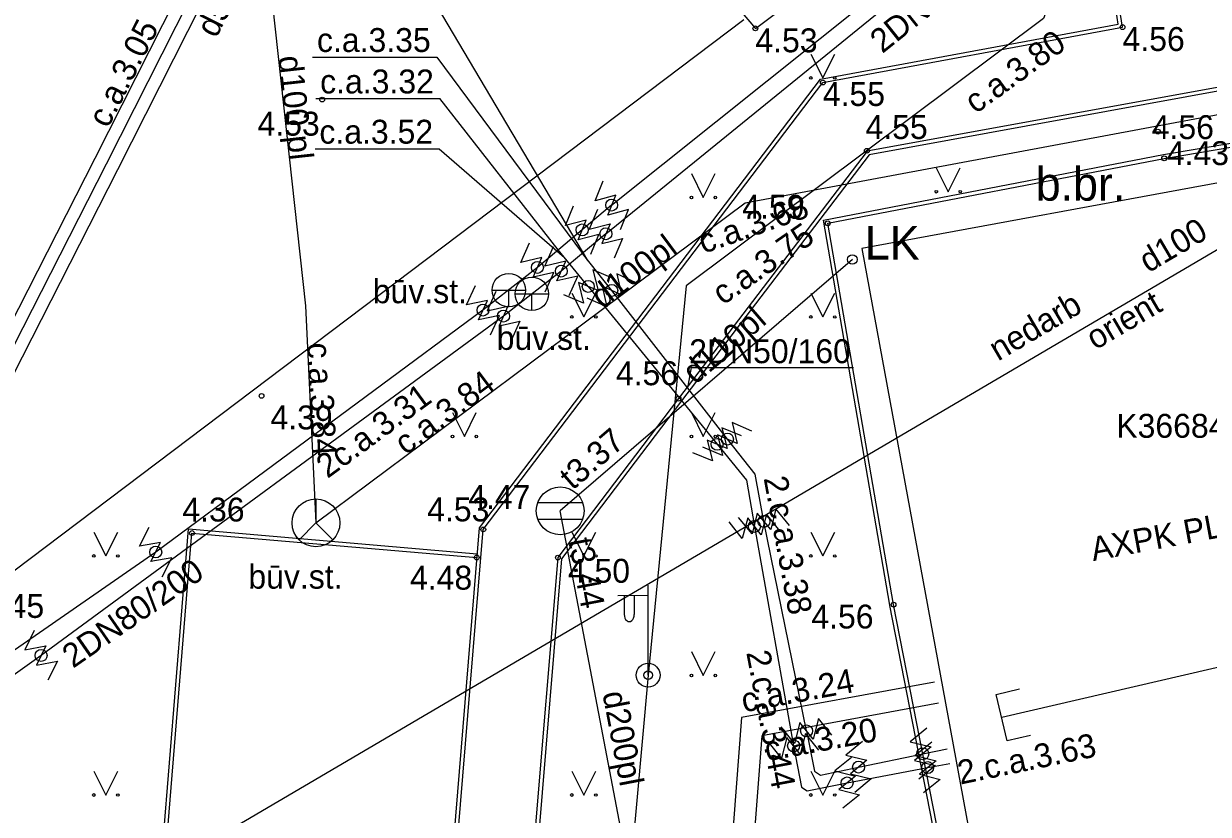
# Model space of a CAD drawing. Extents: x 484635 to 484808, y 278866 to 278977.
# Drawn here: x 484755.78 to 484780.57, y 278882.1 to 278898.63 of the extents above; entities that cross this region are included whole.
import ezdxf

# ---------------------------------------------------------------- set-up
doc = ezdxf.new("R2010")
doc.units = 0
for name, color, linetype in [('APGS_ACRL_####_####_#', 7, 'Continuous'), ('APGS_ELEM_####_####_#', 7, 'Continuous'), ('APGS_ELEM_####_TKST_#', 7, 'Continuous'), ('APGS_VADP_ZSPR_####_I', 7, 'Continuous'), ('BUVE_EKAS_####_####_#', 7, 'Continuous'), ('CELI_CAPM_####_####_#', 7, 'Continuous'), ('CELI_CSEG_####_TKST_#', 7, 'Continuous'), ('CKOM_ELEM_####_####_#', 7, 'Continuous'), ('ELEK_ELEM_####_TKST_#', 7, 'Continuous'), ('ELEK_VADP_ZSPR_TKST_I', 7, 'Continuous'), ('GAZE_VADP_KONT_####_#', 7, 'Continuous'), ('GAZE_VADP_VSP2_####_#', 7, 'Continuous'), ('GAZE_VADP_VSP2_TKST_#', 7, 'Continuous'), ('LKAN_ELEM_####_####_#', 7, 'Continuous'), ('LKAN_ELEM_PAST_TKST_#', 7, 'Continuous'), ('LKAN_VADP_PAST_####_#', 7, 'Continuous'), ('LKAN_VADP_PAST_####_I', 7, 'Continuous'), ('LKAN_VADP_PAST_TKST_I', 7, 'Continuous'), ('NORB_ZOGS_KONT_####_#', 7, 'Continuous'), ('NORB_ZOGS_ZSTP_####_#', 7, 'Continuous'), ('RELJ_AATZ_####_TKST_#', 7, 'Continuous'), ('RELJ_ELEM_####_####_#', 7, 'Continuous'), ('SAKK_ELEM_####_####_#', 7, 'Continuous'), ('SAKK_ELEM_####_TKST_#', 7, 'Continuous'), ('SAKK_KKAN_####_####_I', 7, 'Continuous'), ('SAKK_KKAN_####_TKST_I', 7, 'Continuous'), ('SILT_ELEM_####_####_#', 7, 'Continuous'), ('SILT_ELEM_####_TKST_#', 7, 'Continuous'), ('SILT_VADP_UDEN_####_I', 7, 'Continuous'), ('SILT_VADP_UDEN_TKST_I', 7, 'Continuous'), ('TERT_ELEM_####_####_#', 7, 'Continuous'), ('UDTK_ELEM_####_####_#', 7, 'Continuous'), ('UDTK_VADP_NEDR_####_#', 7, 'Continuous'), ('UDTK_VADP_NEDR_TKST_#', 7, 'Continuous'), ('UDTK_VADP_UDEN_####_I', 7, 'Continuous'), ('UDTK_VADP_UDEN_TKST_I', 7, 'Continuous')]:
    doc.layers.add(name, color=color, linetype=linetype)

msp = doc.modelspace()

# ---------------------------------------------------------------- linework, layer by layer
at = {"layer": 'APGS_ACRL_####_####_#'}
msp.add_lwpolyline([(484777.807, 278900.58), (484777.114, 278898.745), (484769.642, 278893.153), (484768.844, 278885.007), (484767.749, 278872.905), (484767.227, 278866.043)], dxfattribs=at)
at = {"layer": 'APGS_ELEM_####_####_#'}
for p, q in [((484768.844, 278885.007), (484768.844, 278886.89)), ((484768.844, 278886.674), (484768.209, 278886.669)), ((484768.344, 278886.67), (484768.344, 278886.278)), ((484768.554, 278886.672), (484768.554, 278886.278))]:
    msp.add_line(p, q, dxfattribs=at)
for radius in [0.25, 0.09]:
    msp.add_circle((484768.844, 278885.007), radius, dxfattribs=at)
msp.add_ellipse((484768.449, 278886.278), major_axis=(0, 0.151), ratio=0.695971, start_param=1.570796, end_param=4.712389, dxfattribs=at)
at = {"layer": 'APGS_VADP_ZSPR_####_I'}
msp.add_lwpolyline([(484777.807, 278900.58), (484777.114, 278898.745), (484769.642, 278893.153), (484768.844, 278885.007), (484767.749, 278872.905), (484767.227, 278866.043)], dxfattribs=at)
at = {"layer": 'BUVE_EKAS_####_####_#'}
for p, q in [((484784.53, 278895.998), (484773.318, 278893.935)), ((484773.318, 278893.935), (484775.96, 278879.576))]:
    msp.add_line(p, q, dxfattribs=at)
at = {"layer": 'CELI_CAPM_####_####_#'}
for p, q in [((484778.68, 278898.628), (484778.384, 278900.515)), ((484778.771, 278898.563), (484778.475, 278900.45)), ((484772.455, 278897.477), (484778.68, 278898.628)), ((484772.5, 278897.404), (484778.771, 278898.563)), ((484765.319, 278888.086), (484772.455, 278897.477)), ((484765.396, 278888.056), (484772.5, 278897.404)), ((484780.905, 278897.327), (484773.429, 278895.967)), ((484780.92, 278897.248), (484773.473, 278895.893)), ((484779.629, 278895.897), (484785.162, 278896.83)), ((484779.642, 278895.818), (484785.097, 278896.738)), ((484773.429, 278895.967), (484769.481, 278890.791)), ((484773.473, 278895.893), (484769.544, 278890.743)), ((484772.511, 278894.523), (484779.627, 278895.896)), ((484772.603, 278894.459), (484779.642, 278895.818)), ((484773.902, 278886.468), (484772.511, 278894.523)), ((484773.981, 278886.482), (484772.603, 278894.459)), ((484769.481, 278890.791), (484766.957, 278887.466)), ((484769.544, 278890.743), (484767.035, 278887.437)), ((484758.324, 278876.945), (484759.228, 278888.066)), ((484759.228, 278888.066), (484765.267, 278887.548)), ((484764.786, 278881.634), (484765.319, 278888.086)), ((484764.865, 278881.628), (484765.396, 278888.056)), ((484758.41, 278877.018), (484759.301, 278887.98)), ((484759.301, 278887.98), (484765.26, 278887.468)), ((484766.957, 278887.466), (484766.407, 278880.899)), ((484767.035, 278887.437), (484766.487, 278880.893)), ((484775.138, 278880.157), (484773.902, 278886.466)), ((484775.232, 278880.093), (484773.981, 278886.482))]:
    msp.add_line(p, q, dxfattribs=at)
at = {"layer": 'CKOM_ELEM_####_####_#'}
for points in [[(484768.264, 278894.333), (484768.431, 278894.748), (484767.999, 278894.633), (484768.166, 278895.048), (484767.734, 278894.932), (484767.901, 278895.347)], [(484767.646, 278893.814), (484767.813, 278894.228), (484767.381, 278894.114), (484767.548, 278894.528), (484767.116, 278894.414), (484767.284, 278894.828)], [(484767.788, 278894.751), (484767.614, 278894.339), (484768.048, 278894.447), (484767.874, 278894.035), (484768.308, 278894.143), (484768.135, 278893.731)], [(484766.693, 278893.024), (484766.874, 278893.433), (484766.438, 278893.332), (484766.619, 278893.741), (484766.183, 278893.64), (484766.364, 278894.049)], [(484767.191, 278892.946), (484767.373, 278893.355), (484766.937, 278893.256), (484767.12, 278893.664), (484766.684, 278893.565), (484766.866, 278893.973)], [(484768.103, 278893.312), (484767.69, 278893.485), (484767.799, 278893.051), (484767.387, 278893.224), (484767.496, 278892.791), (484767.084, 278892.963)], [(484768.597, 278893.216), (484768.189, 278893.399), (484768.288, 278892.963), (484767.88, 278893.145), (484767.979, 278892.709), (484767.571, 278892.891)], [(484765.545, 278892.128), (484765.734, 278892.534), (484765.296, 278892.441), (484765.484, 278892.847), (484765.047, 278892.754), (484765.235, 278893.159)], [(484765.657, 278893.033), (484765.474, 278892.625), (484765.91, 278892.724), (484765.728, 278892.315), (484766.164, 278892.414), (484765.981, 278892.006)], [(484771.016, 278890.112), (484770.606, 278890.291), (484770.71, 278889.856), (484770.3, 278890.034), (484770.403, 278889.599), (484769.993, 278889.777)], [(484770.798, 278890.012), (484770.385, 278890.184), (484770.496, 278889.75), (484770.082, 278889.922), (484770.193, 278889.488), (484769.78, 278889.66)], [(484771.599, 278888.024), (484771.323, 278888.376), (484771.207, 278887.944), (484770.931, 278888.295), (484770.815, 278887.863), (484770.539, 278888.215)], [(484771.8, 278888.14), (484771.515, 278888.485), (484771.41, 278888.051), (484771.125, 278888.395), (484771.02, 278887.961), (484770.735, 278888.306)], [(484758.676, 278887.062), (484758.88, 278887.459), (484758.439, 278887.385), (484758.644, 278887.782), (484758.203, 278887.707), (484758.408, 278888.105)], [(484756.002, 278885.938), (484755.804, 278885.537), (484756.244, 278885.62), (484756.046, 278885.219), (484756.486, 278885.301), (484756.288, 278884.9)], [(484772.691, 278883.755), (484772.409, 278884.102), (484772.301, 278883.668), (484772.018, 278884.014), (484771.91, 278883.58), (484771.628, 278883.927)], [(484774.673, 278883.895), (484774.329, 278883.609), (484774.764, 278883.505), (484774.42, 278883.22), (484774.855, 278883.116), (484774.511, 278882.83)], [(484772.42, 278883.438), (484772.14, 278883.786), (484772.029, 278883.353), (484771.749, 278883.702), (484771.638, 278883.269), (484771.358, 278883.617)], [(484773.329, 278883.617), (484772.985, 278883.331), (484773.42, 278883.228), (484773.076, 278882.942), (484773.511, 278882.838), (484773.167, 278882.552)], [(484774.784, 278883.604), (484774.435, 278883.324), (484774.869, 278883.213), (484774.52, 278882.933), (484774.953, 278882.822), (484774.605, 278882.542)], [(484773.099, 278883.284), (484772.75, 278883.004), (484773.184, 278882.893), (484772.835, 278882.613), (484773.269, 278882.502), (484772.92, 278882.222)]]:
    msp.add_lwpolyline(points, dxfattribs=at)
for centre in [(484768.082, 278894.84), (484767.465, 278894.321), (484767.961, 278894.241), (484766.529, 278893.537), (484767.029, 278893.46), (484767.593, 278893.138), (484768.084, 278893.054), (484765.39, 278892.644), (484765.819, 278892.519), (484770.505, 278889.945), (484770.289, 278889.836), (484771.268, 278888.223), (484771.069, 278888.119), (484758.542, 278887.583), (484756.145, 278885.419), (484772.159, 278883.841), (484771.889, 278883.528), (484774.592, 278883.362), (484773.248, 278883.085), (484774.694, 278883.073), (484773.009, 278882.753)]:
    msp.add_circle(centre, 0.125, dxfattribs=at)
at = {"layer": 'GAZE_VADP_KONT_####_#'}
for points in [[(484750.477, 278882.479), (484757.277, 278895.824), (484768.894, 278918.779), (484766.279, 278933.523), (484765.094, 278950.654), (484769.76, 278961.533)], [(484751.36, 278883.044), (484757.749, 278895.584), (484769.446, 278918.697), (484766.805, 278933.587), (484765.632, 278950.562), (484770.25, 278961.331)]]:
    msp.add_lwpolyline(points, dxfattribs=at)
at = {"layer": 'GAZE_VADP_VSP2_####_#'}
msp.add_lwpolyline([(484750.918, 278882.762), (484757.513, 278895.704), (484769.17, 278918.738), (484766.542, 278933.555), (484765.363, 278950.608), (484770.005, 278961.432)], dxfattribs=at)
at = {"layer": 'LKAN_ELEM_####_####_#'}
for p, q in [((484766.538, 278888.619), (484767.474, 278888.619)), ((484766.538, 278888.269), (484767.474, 278888.269))]:
    msp.add_line(p, q, dxfattribs=at)
for centre, radius in [((484773.118, 278893.702), 0.1), ((484767.006, 278888.444), 0.5)]:
    msp.add_circle(centre, radius, dxfattribs=at)
at = {"layer": 'LKAN_VADP_PAST_####_#'}
msp.add_lwpolyline([(484768.848, 278878.793), (484767.006, 278888.444)], dxfattribs=at)
at = {"layer": 'LKAN_VADP_PAST_####_I'}
msp.add_lwpolyline([(484773.118, 278893.702), (484767.006, 278888.444)], dxfattribs=at)
at = {"layer": 'NORB_ZOGS_KONT_####_#'}
for p, q in [((484771.089, 278898.537), (484788.785, 278911.787)), ((484770.732, 278898.963), (484771.089, 278898.537))]:
    msp.add_line(p, q, dxfattribs=at)
at = {"layer": 'NORB_ZOGS_ZSTP_####_#'}
msp.add_lwpolyline([(484754.908, 278886.695), (484770.847, 278898.725)], dxfattribs=at)
at = {"layer": 'RELJ_ELEM_####_####_#'}
for centre in [(484771.089, 278898.537), (484778.771, 278898.563), (484772.5, 278897.404), (484762.025, 278897.047), (484779.511, 278896.377), (484773.421, 278895.977), (484779.642, 278895.818), (484772.603, 278894.459), (484760.757, 278890.848), (484769.481, 278890.791), (484765.396, 278888.056), (484759.301, 278887.98), (484765.26, 278887.468), (484766.957, 278887.466), (484773.981, 278886.482)]:
    msp.add_circle(centre, 0.05, dxfattribs=at)
at = {"layer": 'SAKK_ELEM_####_####_#'}
msp.add_line((484761.895, 278888.193), (484762.249, 278887.839), dxfattribs=at)
msp.add_lwpolyline([(484761.895, 278888.693), (484761.895, 278888.193), (484761.541, 278887.839)], dxfattribs=at)
msp.add_circle((484761.895, 278888.193), 0.5, dxfattribs=at)
at = {"layer": 'SAKK_KKAN_####_####_I'}
for points in [[(484760.526, 278903.237), (484761.675, 278892.732), (484761.895, 278888.193)], [(484761.895, 278888.193), (484770.872, 278894.886), (484788.535, 278898.187), (484797.166, 278899.809), (484807.573, 278901.643)]]:
    msp.add_lwpolyline(points, dxfattribs=at)
at = {"layer": 'SILT_ELEM_####_####_#'}
for p, q in [((484765.579, 278893.06), (484766.282, 278893.06)), ((484765.931, 278892.708), (484765.931, 278893.06)), ((484766.061, 278892.984), (484766.764, 278892.984)), ((484766.412, 278892.632), (484766.412, 278892.984))]:
    msp.add_line(p, q, dxfattribs=at)
for centre in [(484765.931, 278893.06), (484766.412, 278892.984)]:
    msp.add_circle(centre, 0.351, dxfattribs=at)
at = {"layer": 'SILT_VADP_UDEN_####_I'}
for p, q in [((484768.082, 278894.84), (484777.455, 278902.334)), ((484767.961, 278894.241), (484777.274, 278901.809)), ((484765.819, 278892.519), (484756.145, 278885.419))]:
    msp.add_line(p, q, dxfattribs=at)
for points in [[(484768.082, 278894.84), (484767.465, 278894.321)], [(484767.465, 278894.321), (484766.529, 278893.537)], [(484767.961, 278894.241), (484767.029, 278893.46)], [(484767.593, 278893.138), (484766.964, 278893.902)], [(484768.084, 278893.054), (484767.47, 278893.829)], [(484766.529, 278893.537), (484765.39, 278892.644)], [(484767.029, 278893.46), (484765.819, 278892.519)], [(484767.593, 278893.138), (484770.289, 278889.836)], [(484770.505, 278889.945), (484768.084, 278893.054)], [(484765.39, 278892.644), (484758.542, 278887.583)], [(484770.289, 278889.836), (484770.906, 278889.086), (484771.069, 278888.119)], [(484771.268, 278888.223), (484771.084, 278889.215), (484770.505, 278889.945)], [(484771.069, 278888.119), (484771.889, 278883.528)], [(484772.159, 278883.841), (484771.268, 278888.223)], [(484758.542, 278887.583), (484752.374, 278883.308)], [(484756.145, 278885.419), (484752.644, 278882.924)], [(484774.92, 278884.42), (484771.223, 278883.74), (484770.922, 278879.839), (484772.816, 278869.49)], [(484772.159, 278883.841), (484772.326, 278882.996), (484772.455, 278882.917), (484773.248, 278883.085)], [(484771.889, 278883.528), (484772.053, 278882.663), (484772.176, 278882.589), (484773.009, 278882.753)], [(484773.248, 278883.085), (484774.592, 278883.362)], [(484774.592, 278883.362), (484775.099, 278883.467)], [(484773.009, 278882.753), (484774.694, 278883.073)], [(484774.694, 278883.073), (484775.155, 278883.161)]]:
    msp.add_lwpolyline(points, dxfattribs=at)
at = {"layer": 'SILT_VADP_UDEN_TKST_I'}
for p, q in [((484767.585, 278893.684), (484764.438, 278898.988)), ((484761.826, 278897.937), (484764.421, 278897.937)), ((484764.421, 278897.937), (484767.47, 278893.829)), ((484761.895, 278897.07), (484764.49, 278897.07)), ((484766.964, 278893.902), (484764.49, 278897.07)), ((484761.879, 278896.019), (484764.474, 278896.019)), ((484764.474, 278896.019), (484767.095, 278893.743)), ((484769.746, 278891.44), (484769.666, 278891.021)), ((484769.746, 278891.44), (484773.142, 278891.44))]:
    msp.add_line(p, q, dxfattribs=at)
at = {"layer": 'TERT_ELEM_####_####_#'}
for p, q in [((484772.25, 278898), (484772.5, 278897.5)), ((484772.5, 278897.5), (484772.75, 278898)), ((484769.75, 278895.5), (484770, 278895)), ((484770, 278895), (484770.25, 278895.5)), ((484774.875, 278895.62), (484775.125, 278895.12)), ((484775.125, 278895.12), (484775.375, 278895.62)), ((484767.25, 278893), (484767.5, 278892.5)), ((484767.5, 278892.5), (484767.75, 278893)), ((484772.25, 278893), (484772.5, 278892.5)), ((484772.5, 278892.5), (484772.75, 278893)), ((484764.75, 278890.5), (484765, 278890)), ((484765, 278890), (484765.25, 278890.5)), ((484769.75, 278890.5), (484770, 278890)), ((484770, 278890), (484770.25, 278890.5)), ((484757.25, 278888), (484757.5, 278887.5)), ((484757.5, 278887.5), (484757.75, 278888)), ((484767.25, 278888), (484767.5, 278887.5)), ((484767.5, 278887.5), (484767.75, 278888)), ((484772.25, 278888), (484772.5, 278887.5)), ((484772.5, 278887.5), (484772.75, 278888)), ((484769.75, 278885.5), (484770, 278885)), ((484770, 278885), (484770.25, 278885.5)), ((484757.25, 278883), (484757.5, 278882.5)), ((484757.5, 278882.5), (484757.75, 278883)), ((484767.25, 278883), (484767.5, 278882.5)), ((484767.5, 278882.5), (484767.75, 278883)), ((484772.25, 278883), (484772.5, 278882.5)), ((484772.5, 278882.5), (484772.75, 278883))]:
    msp.add_line(p, q, dxfattribs=at)
for centre, radius in [((484772.25, 278897.5), 0.028), ((484772.75, 278897.5), 0.0263), ((484769.75, 278895), 0.028), ((484770.25, 278895), 0.0263), ((484774.875, 278895.12), 0.028), ((484775.375, 278895.12), 0.0263), ((484767.25, 278892.5), 0.028), ((484767.75, 278892.5), 0.0263), ((484772.25, 278892.5), 0.028), ((484772.75, 278892.5), 0.0263), ((484764.75, 278890), 0.028), ((484765.25, 278890), 0.0263), ((484769.75, 278890), 0.028), ((484770.25, 278890), 0.0263), ((484757.25, 278887.5), 0.028), ((484757.75, 278887.5), 0.0263), ((484767.25, 278887.5), 0.028), ((484767.75, 278887.5), 0.0263), ((484772.25, 278887.5), 0.028), ((484772.75, 278887.5), 0.0263), ((484769.75, 278885), 0.028), ((484770.25, 278885), 0.0263), ((484757.25, 278882.5), 0.028), ((484757.75, 278882.5), 0.0263), ((484767.25, 278882.5), 0.028), ((484767.75, 278882.5), 0.0263), ((484772.25, 278882.5), 0.028), ((484772.75, 278882.5), 0.0263)]:
    msp.add_circle(centre, radius, dxfattribs=at)
at = {"layer": 'UDTK_ELEM_####_####_#'}
msp.add_lwpolyline([(484776.843, 278883.744), (484776.356, 278883.631), (484776.13, 278884.605), (484776.618, 278884.718)], dxfattribs=at)
at = {"layer": 'UDTK_VADP_NEDR_####_#'}
msp.add_lwpolyline([(484753.238, 278876.403), (484757.275, 278880.118), (484799.521, 278904.942)], dxfattribs=at)
at = {"layer": 'UDTK_VADP_UDEN_####_I'}
for points in [[(484807.573, 278891.378), (484776.243, 278884.118)], [(484774.839, 278884.862), (484770.801, 278884.12), (484770.469, 278879.816), (484772.455, 278868.966)]]:
    msp.add_lwpolyline(points, dxfattribs=at)

# ---------------------------------------------------------------- texts
at = {"layer": 'APGS_ELEM_####_TKST_#'}
for s, rotation, p in [('c.a.3.80', 35.8508, (484775.697, 278896.737)), ('c.a.3.75', 34.7081, (484770.409, 278892.735))]:
    msp.add_text(s, height=0.5, rotation=rotation, dxfattribs=at).set_placement(p)
at = {"layer": 'CELI_CSEG_####_TKST_#'}
msp.add_text('b.br.', height=0.7, dxfattribs=at).set_placement((484776.956, 278894.934))
at = {"layer": 'ELEK_ELEM_####_TKST_#'}
msp.add_text('K366840', height=0.5, dxfattribs=at).set_placement((484778.64, 278889.973))
at = {"layer": 'ELEK_VADP_ZSPR_TKST_I'}
msp.add_text('AXPK PLUS 4x35', height=0.5, rotation=10.529, dxfattribs=at).set_placement((484778.157, 278887.392))
at = {"layer": 'GAZE_VADP_VSP2_TKST_#'}
for s, p in [('d530met', (484759.808, 278898.316)), ('c.a.3.05', (484757.544, 278896.432))]:
    msp.add_text(s, height=0.5, rotation=63.157, dxfattribs=at).set_placement(p)
at = {"layer": 'LKAN_ELEM_####_####_#'}
msp.add_text(' LK', height=0.7, dxfattribs=at).set_placement((484773.118, 278893.702))
at = {"layer": 'LKAN_ELEM_PAST_TKST_#'}
msp.add_text('4.47', height=0.5, dxfattribs=at).set_placement((484765.081, 278888.485))
at = {"layer": 'LKAN_VADP_PAST_TKST_I'}
for s, rotation, p in [('d110pl', 40.7097, (484769.833, 278891.073)), ('t3.37', 40.7097, (484767.264, 278888.863)), ('t3.44', 280.8009, (484767.175, 278887.831)), ('d200pl', 280.8009, (484767.887, 278884.627))]:
    msp.add_text(s, height=0.5, rotation=rotation, dxfattribs=at).set_placement(p)
at = {"layer": 'RELJ_AATZ_####_TKST_#'}
for s, p in [('4.53', (484771.089, 278898.037)), ('4.56', (484778.771, 278898.064)), ('4.55', (484772.5, 278896.914)), ('4.53', (484760.673, 278896.293)), ('4.55', (484773.393, 278896.222)), ('4.56', (484779.382, 278896.221)), (' 4.43', (484779.511, 278895.677)), ('4.59', (484770.814, 278894.555)), ('4.56', (484768.17, 278891.072)), (' 4.39', (484760.757, 278890.148)), ('4.36', (484759.1, 278888.221)), ('4.53', (484764.222, 278888.224)), ('4.48', (484763.863, 278886.796)), ('4.50', (484767.165, 278886.94)), ('4.45', (484754.908, 278886.205)), ('4.56', (484772.26, 278885.983))]:
    msp.add_text(s, height=0.5, dxfattribs=at).set_placement(p)
at = {"layer": 'SAKK_ELEM_####_TKST_#'}
msp.add_text('būv.st.', height=0.5, dxfattribs=at).set_placement((484760.481, 278886.817))
at = {"layer": 'SAKK_KKAN_####_TKST_I'}
for s, rotation, p in [('d100 pl', 276.242, (484761.105, 278897.942)), ('c.a.3.68', 19.3425, (484770.003, 278893.819)), ('d100pl', 36.7072, (484767.884, 278892.658)), ('c.a.3.84', 272.7749, (484761.713, 278891.954)), ('c.a.3.84', 36.7072, (484763.775, 278889.595))]:
    msp.add_text(s, height=0.5, rotation=rotation, dxfattribs=at).set_placement(p)
at = {"layer": 'SILT_ELEM_####_TKST_#'}
for p in [(484763.084, 278892.788), (484765.676, 278891.812)]:
    msp.add_text('būv.st.', height=0.5, dxfattribs=at).set_placement(p)
at = {"layer": 'SILT_VADP_UDEN_TKST_I'}
for s, rotation, p in [('2DN80/200', 38.6435, (484773.745, 278897.999)), ('2c.a.3.31', 36.2761, (484762.137, 278889.11)), ('2.c.a.3.38', 280.4719, (484771.26, 278889.128)), ('2DN80/200', 34.7273, (484756.812, 278885.139)), ('2.c.a.3.44', 280.7336, (484770.897, 278885.482)), ('c.a.3.20', 10.4102, (484771.329, 278883.204)), ('2.c.a.3.63', 11.6758, (484775.377, 278882.717))]:
    msp.add_text(s, height=0.5, rotation=rotation, dxfattribs=at).set_placement(p)
for s, p in [('c.a.3.35', (484761.917, 278898.043)), ('c.a.3.32', (484761.983, 278897.176)), ('c.a.3.52', (484761.967, 278896.125)), ('2DN50/160', (484769.704, 278891.533))]:
    msp.add_text(s, height=0.5, dxfattribs=at).set_placement(p)
at = {"layer": 'UDTK_VADP_NEDR_TKST_#'}
for s, p in [('d100', (484779.309, 278893.413)), ('orient', (484778.2, 278891.799)), ('nedarb', (484776.166, 278891.566))]:
    msp.add_text(s, height=0.5, rotation=30.4385, dxfattribs=at).set_placement(p)
at = {"layer": 'UDTK_VADP_UDEN_TKST_I'}
msp.add_text('c.a.3.24', height=0.5, rotation=10.4102, dxfattribs=at).set_placement((484770.845, 278884.228))

doc.saveas('drawing.dxf')
